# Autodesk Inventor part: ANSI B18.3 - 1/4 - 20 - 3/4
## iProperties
Shininess: 20.0
Length Units: 11268
Angle Units: 11279
Time Units: 11290
Mass Units: 11283
Length Display Precision: 3
Angle Display Precision: 1
Compacted: True
Company: Autodesk
Manager: Lebovitz
Created: 2000-11
Part Number: ANSI B18.3 - 1/4 - 20 - 3/4
Description: Hexagon Socket Head Cap Screw
Document SubType Name: Modeling
Standard: ANSI B18.3 - 1/4 - 20 - 3/4
Designer: The PD Team
Project: Inventor Samples
Checked By: The PD Team
Density: 0.0
Volume: 0.0
Area: 0.0
PropertySet Name: Model Information
Control State: 0
Master: False
Checked Out: False
Author: The PD Team
Revision Number: A
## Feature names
1. Base1
